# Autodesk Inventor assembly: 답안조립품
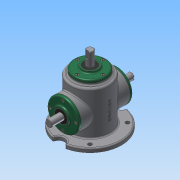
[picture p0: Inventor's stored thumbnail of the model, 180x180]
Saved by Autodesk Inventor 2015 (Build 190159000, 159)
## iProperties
Created: 2018-04
Part Number: 답안조립품
Document SubType Name: Assembly
Designer: user
Author: user
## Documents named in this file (16)
- C:\Users\user\Desktop\480407V1025\답안조립품.iam
- C:\Users\user\Desktop\480407V1025\본체.ipt
- C:\Users\user\Desktop\480407V1025\메인 축.ipt
- 메인 축.ipt
- C:\Users\user\Desktop\480407V1025\커버.ipt
- C:\Users\user\Desktop\480407V1025\오일 실.ipt
- 오일 실.ipt
- C:\Users\user\Desktop\480407V1025\베어링 6203.ipt
- C:\Users\user\Desktop\480407V1025\볼트 M4.ipt
- 볼트 M4.ipt
- C:\Users\user\Desktop\480407V1025\메인 베벨기어.ipt
- C:\Users\user\Desktop\480407V1025\키 5x5.ipt
- C:\Users\user\Desktop\480407V1025\서브 축.ipt
- 서브 축.ipt
- C:\Users\user\Desktop\480407V1025\키 4x4.ipt
- C:\Users\user\Desktop\480407V1025\서브 베벨기어.ipt
